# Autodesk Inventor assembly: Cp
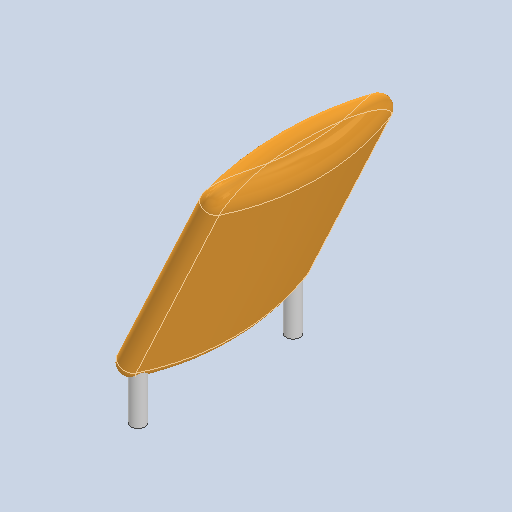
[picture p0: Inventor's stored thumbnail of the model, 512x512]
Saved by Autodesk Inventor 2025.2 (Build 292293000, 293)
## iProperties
Created: 2025-04
Part Number: Cp
Description: PART--DESC
Document SubType Name: Assembly
Designer: BennF
Author: BennF
Revision Number: NONE
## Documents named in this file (3)
- C:\Users\BennF\Nextcloud\Benutzer\CNC JarBeRi\existing parts\Electronics\RepRap A4988 Shied (USE WITHOUT ARDUINO)\reprap-a4988-1.snapshot.1\RepRap\RepRap\Cp_1.iam
- C:\Users\BennF\Nextcloud\Benutzer\CNC JarBeRi\existing parts\Electronics\RepRap A4988 Shied (USE WITHOUT ARDUINO)\reprap-a4988-1.snapshot.1\RepRap\RepRap\Cp Geometry.ipt
- C:\Users\BennF\Nextcloud\Benutzer\CNC JarBeRi\existing parts\Electronics\RepRap A4988 Shied (USE WITHOUT ARDUINO)\reprap-a4988-1.snapshot.1\RepRap\RepRap\pin16.ipt
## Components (2 placed, 2 different names)
1. Cp Geometry
2. pin16
